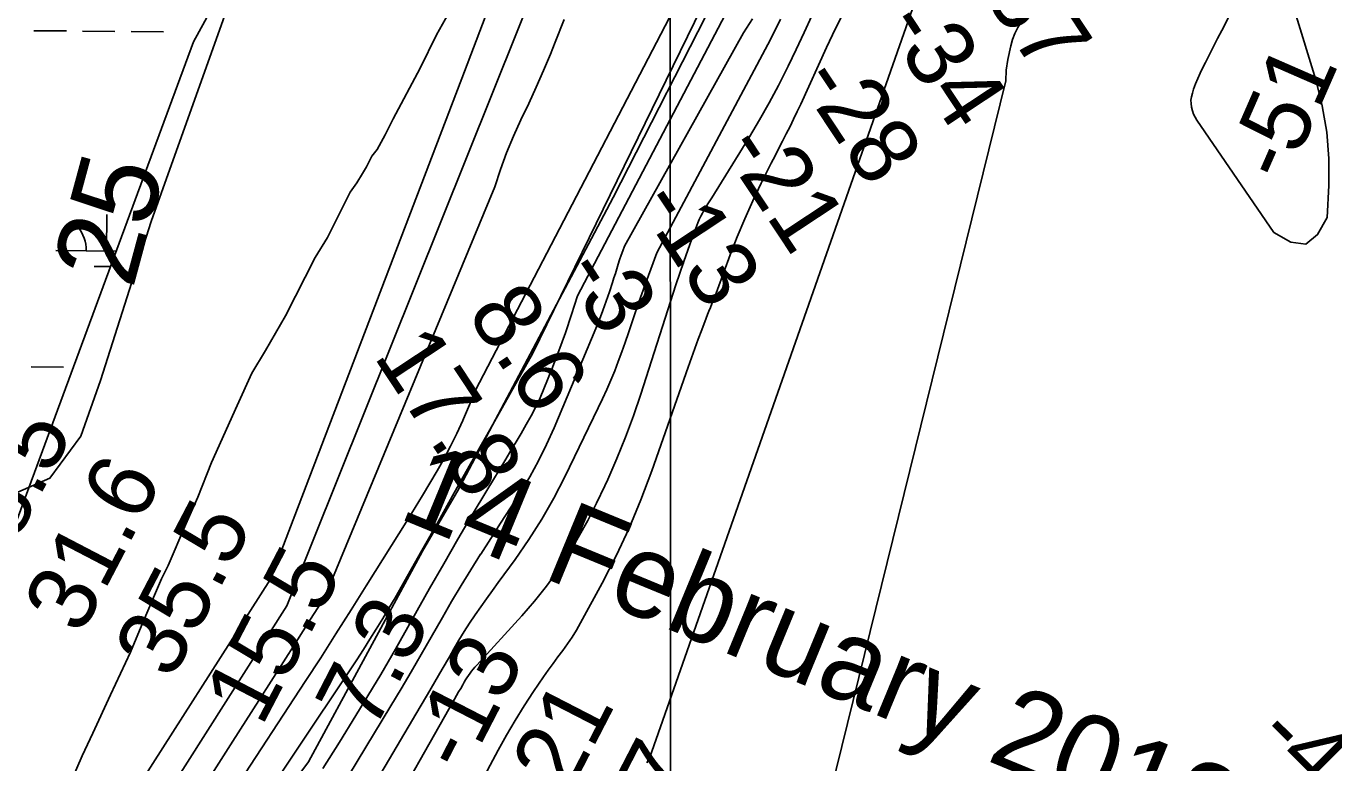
# Model space of a CAD drawing. Extents: x 3271442 to 3309282, y 752266 to 777610.
# Drawn here: x 3290683 to 3291976, y 767420 to 768149 of the extents above; entities that cross this region are included whole.
import ezdxf

# ---------------------------------------------------------------- set-up
doc = ezdxf.new("R2010")
doc.units = 0
for name, color, linetype in [('V-GRID-MAJR', 7, 'Continuous'), ('V-RIVR-EDGE', 7, 'Continuous'), ('V-RIVR-RANG', 7, 'Continuous'), ('V-RIVR-RANG-IDEN', 7, 'Continuous'), ('V-SITE-VEGE', 7, 'Continuous'), ('V-TOPO-DPTH', 7, 'Continuous'), ('V-TOPO-MAJR', 7, 'Continuous'), ('V-TOPO-MAJR-IDEN', 7, 'Continuous'), ('V-TOPO-MINR', 7, 'Continuous'), ('V-TOPO-WATR', 7, 'Continuous'), ('V-WETL-SWMP', 7, 'Continuous')]:
    doc.layers.add(name, color=color, linetype=linetype)

msp = doc.modelspace()

# ---------------------------------------------------------------- linework, layer by layer
at = {"layer": 'V-GRID-MAJR'}
msp.add_spline([(3291322.7, 757646.2), (3291320.9, 763704.7), (3291319.2, 769766.6), (3291317.4, 775828.6), (3291317.4, 775832)], degree=3, dxfattribs=at)
at = {"layer": 'V-RIVR-EDGE'}
msp.add_lwpolyline([(3291369.8, 768188), (3291263.2, 767979.2), (3291241.8, 767938.8), (3291109.5, 767688.8), (3291075, 767629.3), (3290962.3, 767420.9), (3290928.8, 767376.2)], dxfattribs=at)
at = {"layer": 'V-SITE-VEGE'}
msp.add_lwpolyline([(3291100.5, 768161.3), (3291088.6, 768140.2), (3291072.6, 768107.2), (3291046, 768057.1), (3291038, 768041.3), (3291030, 768026.8), (3291024.7, 768020.2), (3291019.4, 768009.7), (3291015.4, 768003.1), (3291010, 767993.8), (3291003.4, 767984.6), (3290980.8, 767939.8), (3290968.8, 767920), (3290939.5, 767862), (3290919.6, 767827.7), (3290906.3, 767805.3), (3290891.6, 767773.6), (3290866.3, 767716.9), (3290852.9, 767682.6), (3290840.9, 767656.2), (3290823.6, 767615.3), (3290817, 767602.1), (3290798.3, 767558.6), (3290786.3, 767529.5), (3290766.3, 767487.3), (3290749, 767449.1), (3290738.3, 767426.7), (3290723.7, 767392.4)], dxfattribs=at)
at = {"layer": 'V-TOPO-DPTH'}
for p, q in [((3291660.3, 768141.6), (3291663.2, 768147.4)), ((3291660.3, 768141.6), (3291663.2, 768147.4)), ((3291663.2, 768147.4), (3291666.5, 768153)), ((3291663.2, 768147.4), (3291666.5, 768153)), ((3291656.3, 768129.2), (3291658.1, 768135.5)), ((3291656.3, 768129.2), (3291658.1, 768135.5)), ((3291658.1, 768135.5), (3291660.3, 768141.6)), ((3291658.1, 768135.5), (3291660.3, 768141.6)), ((3291653.4, 768115.8), (3291656.3, 768129.2)), ((3291653.4, 768115.8), (3291656.3, 768129.2)), ((3291651.9, 768105.2), (3291653.4, 768115.8)), ((3291651.9, 768105.2), (3291653.4, 768115.8)), ((3291651.3, 768094.6), (3291651.9, 768105.2)), ((3291651.3, 768094.6), (3291651.9, 768105.2)), ((3291472.5, 767368.2), (3291651.3, 768094.6)), ((3291472.5, 767368.2), (3291651.3, 768094.6))]:
    msp.add_line(p, q, dxfattribs=at)
for points in [[(3292114.7, 769544.5), (3291910.4, 769101.8), (3291902.7, 769082.9), (3291896.2, 769063.6), (3291891.6, 769043.8), (3291582.9, 768230), (3291581.1, 768229.2), (3291299.1, 767424.5), (3291297.8, 767422.2), (3291296.5, 767419.8)], [(3292114.7, 769544.5), (3291910.4, 769101.8), (3291902.7, 769082.9), (3291896.2, 769063.6), (3291891.6, 769043.8), (3291582.9, 768230), (3291581.1, 768229.2), (3291299.1, 767424.5), (3291297.8, 767422.2), (3291296.5, 767419.8)], [(3291385.6, 768285.5), (3291126.9, 767788.1), (3291121.4, 767774.2), (3291115.5, 767760.4), (3291114.7, 767758.6), (3291108.8, 767745.9), (3291102.6, 767733.3), (3291096.1, 767721), (3291089.2, 767708.7), (3291082.2, 767696.6), (3291075, 767684.5), (3291067.7, 767672.5), (3291060.4, 767660.6), (3291019.3, 767594.9), (3291004.4, 767571.2), (3290989.3, 767547.5), (3290974.2, 767523.9), (3290958.9, 767500.4), (3290888.6, 767392.7)], [(3291387.5, 768186.1), (3291228, 767881.9), (3291222.2, 767863.6), (3291216.1, 767845.4), (3291209.5, 767827.4), (3291202.6, 767809.5), (3291194.9, 767790.1), (3291191, 767781), (3291186.8, 767772), (3291182.3, 767763.2), (3291177.4, 767754.5), (3291172.4, 767745.9), (3291167.3, 767737.4), (3291162.3, 767728.8), (3291157.1, 767720.3), (3291138.4, 767689.3), (3291124, 767665.2), (3291109.8, 767641.1), (3291095.8, 767616.8), (3291081.9, 767592.4), (3291048.1, 767532.4), (3291044.5, 767526.1), (3291040.9, 767519.8), (3291037.2, 767513.6), (3291033.5, 767507.4), (3291009, 767466.8), (3290992.7, 767440.4), (3290976.2, 767414.3)], [(3290976.2, 767414.3), (3290992.7, 767440.4), (3291009, 767466.8), (3291033.5, 767507.4), (3291037.2, 767513.6), (3291040.9, 767519.8), (3291044.5, 767526.1), (3291048.1, 767532.4), (3291081.9, 767592.4), (3291095.8, 767616.8), (3291109.8, 767641.1), (3291124, 767665.2), (3291138.4, 767689.3), (3291157.1, 767720.3), (3291162.3, 767728.8), (3291167.3, 767737.4), (3291172.4, 767745.9), (3291177.4, 767754.5), (3291182.3, 767763.2), (3291186.8, 767772), (3291191, 767781), (3291194.9, 767790.1), (3291202.6, 767809.5), (3291209.5, 767827.4), (3291216.1, 767845.4), (3291222.2, 767863.6), (3291228, 767881.9), (3291387.5, 768186.1)], [(3290775.8, 766729.5), (3291149.7, 767432.5), (3291157.8, 767447.3), (3291166.4, 767461.9), (3291175.3, 767476.2), (3291184.6, 767490.4), (3291194.6, 767505), (3291199.2, 767511.6), (3291203.9, 767518.2), (3291208.7, 767524.7), (3291213.5, 767531.2), (3291218.2, 767537.7), (3291222.7, 767544.4), (3291226.9, 767551.3), (3291230.9, 767558.3), (3291252.3, 767597.6), (3291266.2, 767624.7), (3291279.2, 767652.2), (3291290.8, 767680.2), (3291301.6, 767708.7), (3291337.3, 767811.3), (3291340.6, 767820.6), (3291344, 767829.9), (3291347.4, 767839.2), (3291350.9, 767848.4), (3291355.2, 767859.8), (3291356.6, 767863.4), (3291358, 767866.9), (3291359.4, 767870.5), (3291360.9, 767874), (3291362.3, 767877.6), (3291363.7, 767881.2), (3291365.1, 767884.7), (3291366.4, 767888.3), (3291378.9, 767922.4), (3291385.9, 767940.4), (3291393.3, 767958.3), (3291401.2, 767975.9), (3291409.6, 767993.3), (3291419.6, 768013.3), (3291423.3, 768020.6), (3291426.9, 768027.9), (3291430.7, 768035.1), (3291434.4, 768042.3), (3291438.1, 768049.6), (3291441.7, 768056.8), (3291445.2, 768064.2), (3291448.7, 768071.6), (3291474.1, 768127.8), (3291483.1, 768146.6), (3291492.6, 768165.1)], [(3290775.8, 766729.5), (3291149.7, 767432.5), (3291157.8, 767447.3), (3291166.4, 767461.9), (3291175.3, 767476.2), (3291184.6, 767490.4), (3291194.6, 767505), (3291199.2, 767511.6), (3291203.9, 767518.2), (3291208.7, 767524.7), (3291213.5, 767531.2), (3291218.2, 767537.7), (3291222.7, 767544.4), (3291226.9, 767551.3), (3291230.9, 767558.3), (3291252.3, 767597.6), (3291266.2, 767624.7), (3291279.2, 767652.2), (3291290.8, 767680.2), (3291301.6, 767708.7), (3291337.3, 767811.3), (3291340.6, 767820.6), (3291344, 767829.9), (3291347.4, 767839.2), (3291350.9, 767848.4), (3291355.2, 767859.8), (3291356.6, 767863.4), (3291358, 767866.9), (3291359.4, 767870.5), (3291360.9, 767874), (3291362.3, 767877.6), (3291363.7, 767881.2), (3291365.1, 767884.7), (3291366.4, 767888.3), (3291378.9, 767922.4), (3291385.9, 767940.4), (3291393.3, 767958.3), (3291401.2, 767975.9), (3291409.6, 767993.3), (3291419.6, 768013.3), (3291423.3, 768020.6), (3291426.9, 768027.9), (3291430.7, 768035.1), (3291434.4, 768042.3), (3291438.1, 768049.6), (3291441.7, 768056.8), (3291445.2, 768064.2), (3291448.7, 768071.6), (3291474.1, 768127.8), (3291483.1, 768146.6), (3291492.6, 768165.1)], [(3291428.7, 768155.6), (3291418.9, 768135.5), (3291306.6, 767924.6), (3291300.5, 767908.4), (3291294.5, 767892.1), (3291288.8, 767875.7), (3291283.2, 767859.2), (3291278.6, 767845.2), (3291275.3, 767835.8), (3291272, 767826.4), (3291268.4, 767817), (3291264.8, 767807.7), (3291261, 767798.5), (3291257, 767789.3), (3291252.9, 767780.2), (3291248.6, 767771.2), (3291215.5, 767702.9), (3291204.5, 767681.7), (3291192.8, 767660.9), (3291180, 767640.8), (3291166.4, 767621.1), (3291149.8, 767598.4), (3291144, 767590.4), (3291138.2, 767582.3), (3291132.5, 767574.3), (3291126.8, 767566.2), (3291121.3, 767558), (3291115.9, 767549.7), (3291110.8, 767541.2), (3291105.8, 767532.7), (3291101.4, 767524.9), (3291094.3, 767512.5), (3291087.1, 767500), (3291079.9, 767487.6), (3291072.6, 767475.2), (3290831.8, 767066.6)], [(3290831.8, 767066.6), (3291072.6, 767475.2), (3291079.9, 767487.6), (3291087.1, 767500), (3291094.3, 767512.5), (3291101.4, 767524.9), (3291105.8, 767532.7), (3291110.8, 767541.2), (3291115.9, 767549.7), (3291121.3, 767558), (3291126.8, 767566.2), (3291132.5, 767574.3), (3291138.2, 767582.3), (3291144, 767590.4), (3291149.8, 767598.4), (3291166.4, 767621.1), (3291180, 767640.8), (3291192.8, 767660.9), (3291204.5, 767681.7), (3291215.5, 767702.9), (3291248.6, 767771.2), (3291252.9, 767780.2), (3291257, 767789.3), (3291261, 767798.5), (3291264.8, 767807.7), (3291268.4, 767817), (3291272, 767826.4), (3291275.3, 767835.8), (3291278.6, 767845.2), (3291283.2, 767859.2), (3291288.8, 767875.7), (3291294.5, 767892.1), (3291300.5, 767908.4), (3291306.6, 767924.6), (3291418.9, 768135.5), (3291428.7, 768155.6)]]:
    msp.add_lwpolyline(points, dxfattribs=at)
at = {"layer": 'V-TOPO-MAJR'}
for points in [[(3289678.6, 767417), (3289709, 767447.3), (3289816.8, 767480.1), (3290184.3, 767559.3), (3290408.1, 767619.5), (3290538, 767641.3), (3290637.5, 767671.4), (3290706.6, 767701.6), (3290737, 767743), (3290756.5, 767798.2), (3290806.6, 767955.4), (3290998.5, 768493.5), (3291042.8, 768534.8), (3291078.7, 768531.9), (3291117.3, 768523.6), (3291161.4, 768501.4), (3291205.5, 768468.1), (3291227.5, 768429.4), (3291230.2, 768404.5), (3291116.3, 768103.8), (3290924.5, 767601.7), (3290486.5, 766915.1)], [(3291948, 767933.2), (3291959.6, 767942.5), (3291969, 767959.5), (3291970.7, 767991.2), (3291970.7, 768017.7), (3291968.8, 768044), (3291964.2, 768070), (3291957.7, 768095.7), (3291937, 768163.2)], [(3291872.4, 768159.4), (3291864.8, 768144.4), (3291860.8, 768136.5), (3291856.8, 768128.7), (3291852.8, 768120.8), (3291848.7, 768112.9), (3291845.8, 768107.3), (3291843.4, 768102.2), (3291841.1, 768097), (3291839, 768091.8), (3291837.1, 768086.4), (3291835.8, 768082.4), (3291834.9, 768079), (3291834.4, 768075.6), (3291834.5, 768072.1), (3291834.9, 768068.6), (3291835.8, 768065.1), (3291837, 768061.8), (3291838.5, 768058.6), (3291840.3, 768055.6), (3291916.4, 767944.6), (3291933.2, 767935.1), (3291948, 767933.2)]]:
    msp.add_lwpolyline(points, dxfattribs=at)
at = {"layer": 'V-TOPO-MINR'}
for p, q in [((3291663.2, 768147.4), (3291660.3, 768141.6)), ((3291666.5, 768153), (3291663.2, 768147.4)), ((3291658.1, 768135.5), (3291656.3, 768129.2)), ((3291660.3, 768141.6), (3291658.1, 768135.5)), ((3291656.3, 768129.2), (3291653.4, 768115.8)), ((3291653.4, 768115.8), (3291651.9, 768105.2)), ((3291651.9, 768105.2), (3291651.3, 768094.6)), ((3291651.3, 768094.6), (3291472.5, 767368.2))]:
    msp.add_line(p, q, dxfattribs=at)
for points in [[(3292114.7, 769544.5), (3291910.4, 769101.8), (3291902.7, 769082.9), (3291896.2, 769063.6), (3291891.6, 769043.8), (3291582.9, 768230), (3291581.1, 768229.2), (3291299.1, 767424.5), (3291297.8, 767422.2), (3291296.5, 767419.8)], [(3291505.1, 769133.3), (3291489.2, 769080.5), (3291471.4, 769022.1), (3291453.1, 768963.9), (3291434.2, 768905.8), (3291414.9, 768847.8), (3291262.4, 768396.6), (3291256.7, 768379.6), (3291251, 768362.5), (3291245.4, 768345.5), (3291239.8, 768328.4), (3291222.2, 768274.4), (3291217.6, 768261.2), (3291212.7, 768248.2), (3291207.3, 768235.3), (3291201.5, 768222.6), (3291195, 768210.3), (3290940.9, 767575.3), (3290585.6, 767016.2)], [(3291385.6, 768285.5), (3291126.9, 767788.1), (3291121.4, 767774.2), (3291115.5, 767760.4), (3291114.7, 767758.6), (3291108.8, 767745.9), (3291102.6, 767733.3), (3291096.1, 767721), (3291089.2, 767708.7), (3291082.2, 767696.6), (3291075, 767684.5), (3291067.7, 767672.5), (3291060.4, 767660.6), (3291019.3, 767594.9), (3291004.4, 767571.2), (3290989.3, 767547.5), (3290974.2, 767523.9), (3290958.9, 767500.4), (3290888.6, 767392.7)], [(3291378.4, 768224.1), (3291184, 767825.2), (3291138.5, 767744.2), (3291122.4, 767715.6), (3291106.3, 767687), (3291090.2, 767658.5), (3291074.1, 767629.9), (3291053.7, 767593.7), (3291047.7, 767583.3), (3291041.7, 767572.9), (3291035.5, 767562.6), (3291029.2, 767552.3), (3291022.8, 767542.1), (3291016.4, 767532), (3291009.8, 767521.9), (3291003.2, 767511.8), (3290796.4, 767201.9)], [(3291492.6, 768165.1), (3291483.1, 768146.6), (3291474.1, 768127.8), (3291448.7, 768071.6), (3291445.2, 768064.2), (3291441.7, 768056.8), (3291438.1, 768049.6), (3291434.4, 768042.3), (3291430.7, 768035.1), (3291426.9, 768027.9), (3291423.3, 768020.6), (3291419.6, 768013.3), (3291409.6, 767993.3), (3291401.2, 767975.9), (3291393.3, 767958.3), (3291385.9, 767940.4), (3291378.9, 767922.4), (3291366.4, 767888.3), (3291365.1, 767884.7), (3291363.7, 767881.2), (3291362.3, 767877.6), (3291360.9, 767874), (3291359.4, 767870.5), (3291358, 767866.9), (3291356.6, 767863.4), (3291355.2, 767859.8), (3291350.9, 767848.4), (3291347.4, 767839.2), (3291344, 767829.9), (3291340.6, 767820.6), (3291337.3, 767811.3), (3291301.6, 767708.7), (3291290.8, 767680.2), (3291279.2, 767652.2), (3291266.2, 767624.7), (3291252.3, 767597.6), (3291230.9, 767558.3), (3291226.9, 767551.3), (3291222.7, 767544.4), (3291218.2, 767537.7), (3291213.5, 767531.2), (3291208.7, 767524.7), (3291203.9, 767518.2), (3291199.2, 767511.6), (3291194.6, 767505), (3291184.6, 767490.4), (3291175.3, 767476.2), (3291166.4, 767461.9), (3291157.8, 767447.3), (3291149.7, 767432.5), (3290775.8, 766729.5)], [(3291428.7, 768155.6), (3291418.9, 768135.5), (3291306.6, 767924.6), (3291300.5, 767908.4), (3291294.5, 767892.1), (3291288.8, 767875.7), (3291283.2, 767859.2), (3291278.6, 767845.2), (3291275.3, 767835.8), (3291272, 767826.4), (3291268.4, 767817), (3291264.8, 767807.7), (3291261, 767798.5), (3291257, 767789.3), (3291252.9, 767780.2), (3291248.6, 767771.2), (3291215.5, 767702.9), (3291204.5, 767681.7), (3291192.8, 767660.9), (3291180, 767640.8), (3291166.4, 767621.1), (3291149.8, 767598.4), (3291144, 767590.4), (3291138.2, 767582.3), (3291132.5, 767574.3), (3291126.8, 767566.2), (3291121.3, 767558), (3291115.9, 767549.7), (3291110.8, 767541.2), (3291105.8, 767532.7), (3291101.4, 767524.9), (3291094.3, 767512.5), (3291087.1, 767500), (3291079.9, 767487.6), (3291072.6, 767475.2), (3290831.8, 767066.6)], [(3291214.8, 768155.3), (3291206, 768132.9), (3291201.3, 768121.2), (3291194.4, 768104.8), (3291187.3, 768088.4), (3291179.9, 768072.2), (3291172.2, 768056.1), (3291164.8, 768040), (3291158, 768023.6), (3291152, 768006.9), (3291146.5, 767989.9), (3290978.6, 767584.8), (3290971.5, 767573.3), (3290964.3, 767561.9), (3290957, 767550.4), (3290949.8, 767539), (3290913.1, 767481.6), (3290887.5, 767441.5), (3290861.9, 767401.4)], [(3291401, 768155.9), (3291392.3, 768142.2), (3291274.6, 767931), (3291272.8, 767926.6), (3291271.2, 767922.2), (3291269.7, 767917.7), (3291268.2, 767913.2), (3291266.8, 767908.7), (3291265.5, 767904.2), (3291264, 767899.7), (3291262.6, 767895.2), (3291259.6, 767885.8), (3291256.5, 767876.7), (3291253.2, 767867.6), (3291249.8, 767858.6), (3291246.2, 767849.6), (3291204.9, 767751.4), (3291197.5, 767734.9), (3291189.6, 767718.7), (3291180.8, 767703), (3291171.6, 767687.5), (3291161.9, 767672.2), (3291152.1, 767656.9), (3291142.3, 767641.7), (3291132.5, 767626.5), (3291132.3, 767626.2), (3291122.6, 767610.8), (3291113, 767595.3), (3291103.6, 767579.6), (3291094.5, 767563.8), (3291083.4, 767544.3), (3291073.6, 767527.1), (3291063.7, 767510.1), (3291053.7, 767493.1), (3291043.6, 767476.2), (3290976.9, 767366.1)], [(3291459.6, 768159.1), (3291452.1, 768142.4), (3291444.3, 768125.8), (3291436.4, 768109.3), (3291435.4, 768107.3), (3291426.6, 768090), (3291417.5, 768072.9), (3291407.9, 768056), (3291398, 768039.4), (3291360.8, 767979), (3291358.9, 767976), (3291357, 767972.9), (3291355.2, 767969.9), (3291353.3, 767966.9), (3291351.5, 767963.9), (3291349.8, 767960.8), (3291348.4, 767957.6), (3291347, 767954.3), (3291341.1, 767938.4), (3291337, 767927.1), (3291333, 767915.8), (3291329.1, 767904.4), (3291325.4, 767893), (3291290.6, 767784.6), (3291283.3, 767763.2), (3291275.5, 767742), (3291267, 767721), (3291258, 767700.3), (3291255.1, 767694), (3291246.9, 767676.7), (3291238.2, 767659.6), (3291228.8, 767642.8), (3291219.1, 767626.3), (3291208.5, 767610.2), (3291197.5, 767594.6), (3291185.5, 767579.7), (3291173, 767565.2), (3291128.5, 767516.6), (3291126.7, 767514.6), (3291125, 767512.6), (3291123.4, 767510.6), (3291121.8, 767508.5), (3291120.3, 767506.3), (3291118.8, 767504.1), (3291117.4, 767501.9), (3291116, 767499.6), (3291114.6, 767497.1), (3291112.6, 767493.5), (3291110.5, 767490), (3291108.5, 767486.4), (3291106.5, 767482.8), (3291033, 767353.1)]]:
    msp.add_lwpolyline(points, dxfattribs=at)
at = {"layer": 'V-TOPO-WATR'}
msp.add_lwpolyline([(3291387.5, 768186.1), (3291228, 767881.9), (3291222.2, 767863.6), (3291216.1, 767845.4), (3291209.5, 767827.4), (3291202.6, 767809.5), (3291194.9, 767790.1), (3291191, 767781), (3291186.8, 767772), (3291182.3, 767763.2), (3291177.4, 767754.5), (3291172.4, 767745.9), (3291167.3, 767737.4), (3291162.3, 767728.8), (3291157.1, 767720.3), (3291138.4, 767689.3), (3291124, 767665.2), (3291109.8, 767641.1), (3291095.8, 767616.8), (3291081.9, 767592.4), (3291048.1, 767532.4), (3291044.5, 767526.1), (3291040.9, 767519.8), (3291037.2, 767513.6), (3291033.5, 767507.4), (3291009, 767466.8), (3290992.7, 767440.4), (3290976.2, 767414.3)], dxfattribs=at)
at = {"layer": 'V-WETL-SWMP'}
for p, q in [((3291123, 768635.4), (3290848.5, 768133.2)), ((3290690.8, 768144.2), (3290722.8, 768144)), ((3290738.8, 768143.8), (3290770.8, 768143.6)), ((3290786.8, 768143.4), (3290818.8, 768143.2)), ((3290848.5, 768133.2), (3290564.5, 767364.1)), ((3290762.4, 767926.4), (3290762.7, 767962.4)), ((3290712.4, 767926.8), (3290772.1, 767926.3)), ((3290750.3, 767911.1), (3290766.4, 767910.9)), ((3290688, 767811.6), (3290720, 767811.3))]:
    msp.add_line(p, q, dxfattribs=at)
msp.add_arc((3290707.2, 767927.3), 35.2, 358.7563, 40.2999, dxfattribs=at)

# ---------------------------------------------------------------- texts
at = {"layer": 'V-RIVR-RANG'}
for s, rotation, p in [('-37', 303.4838, (3291612.3, 768204.6)), ('-34', 303.4838, (3291528.9, 768149.4)), ('-51', 66.3941, (3291928.6, 767991.8)), ('-28', 303.4838, (3291445.3, 768094.6)), ('-21', 303.4838, (3291369.7, 768027.6)), ('-13', 303.4838, (3291286.1, 767972.8)), ('-3', 303.4838, (3291211, 767905.1)), ('8.6', 303.4838, (3291117.8, 767864.6)), ('17.8', 303.4838, (3291025.8, 767822.4)), ('28.5', 62.4383, (3290649.4, 767592.7)), ('31.6', 62.4383, (3290737.3, 767545)), ('35.5', 62.4383, (3290826.9, 767500.6)), ('15.5', 62.4383, (3290915.7, 767454.5)), ('7.3', 62.7191, (3291026.2, 767449.4)), ('-13', 62.7191, (3291117.1, 767407.6)), ('-21', 62.7191, (3291206, 767361.7)), ('-48', 315.2556, (3291896.1, 767443.6)), ('-27', 62.7191, (3291288.3, 767303.3))]:
    msp.add_text(s, height=67, rotation=rotation, dxfattribs=at).set_placement(p)
at = {"layer": 'V-RIVR-RANG-IDEN'}
msp.add_text('14 February 2012     W.S.  35.7', height=83, rotation=337.5804, dxfattribs=at).set_placement((3291049.3, 767662.8))
at = {"layer": 'V-TOPO-MAJR-IDEN'}
msp.add_text('25', height=83, rotation=74.8867, dxfattribs=at).set_placement((3290788.3, 767887.6))

doc.saveas('drawing.dxf')
